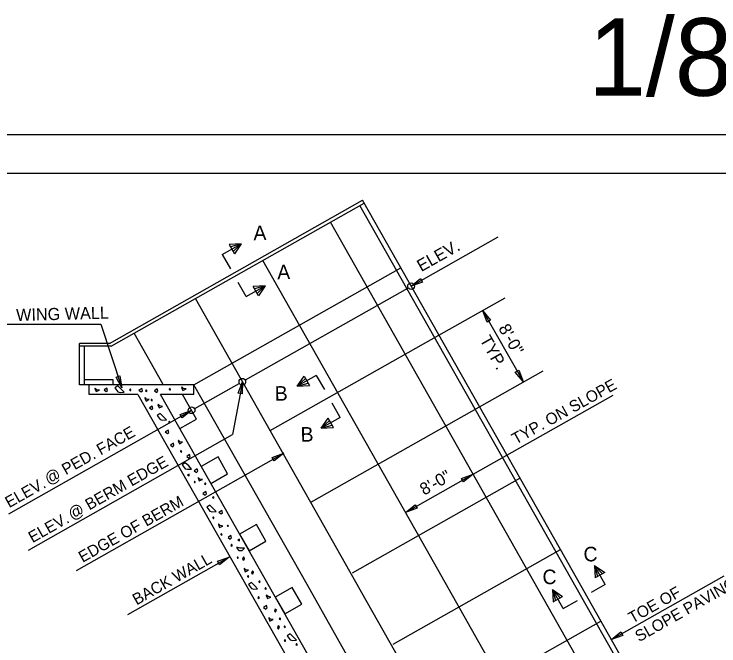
# Model space of a CAD drawing. Extents: x 0 to 272, y 0 to 188.
# Drawn here: x 160.5 to 233.2, y 123.2 to 188.4 of the extents above; entities that cross this region are included whole.
import ezdxf

# ---------------------------------------------------------------- set-up
doc = ezdxf.new("R2010")
doc.units = 0
for name, color, linetype in [('BORDER_ANNO_Cutsheet', 7, 'Continuous'), ('BRDG_ANNO_Anno-Sheet', 7, 'Continuous'), ('BRDG_ANNO_General-Notes', 7, 'Continuous'), ('BRDG_BASE_Hidden-Line', 7, 'Continuous'), ('BRDG_BASE_Obj-Line', 7, 'Continuous'), ('BRDG_BASE_Pattern', 7, 'Continuous')]:
    doc.layers.add(name, color=color, linetype=linetype)

msp = doc.modelspace()

# ---------------------------------------------------------------- linework, layer by layer
at = {"layer": 'BORDER_ANNO_Cutsheet'}
msp.add_lwpolyline([(0, 176), (272, 176), (272, 0), (0, 0)], close=True, dxfattribs=at)
at = {"layer": 'BRDG_ANNO_Anno-Sheet'}
msp.add_lwpolyline([(12, 172), (268, 172), (268, 4), (12, 4)], close=True, dxfattribs=at)
at = {"layer": 'BRDG_ANNO_General-Notes'}
for p, q in [((201.472, 160.347), (210.464, 165.434)), ((182.008, 163.614), (183.967, 164.721)), ((183.967, 164.721), (182.711, 164.657)), ((182.711, 164.657), (182.988, 164.167)), ((183.967, 164.721), (182.849, 164.412)), ((183.967, 164.721), (183.126, 163.923)), ((183.967, 164.721), (183.265, 163.678)), ((182.008, 163.614), (182.839, 162.145)), ((182.988, 164.167), (183.265, 163.678)), ((184.482, 159.277), (183.651, 160.745)), ((201.472, 160.347), (202.458, 161.144)), ((202.663, 160.781), (201.472, 160.347)), ((202.458, 161.144), (202.663, 160.781)), ((184.383, 150.679), (201.141, 160.16)), ((184.482, 159.277), (186.44, 160.385)), ((186.44, 160.385), (185.184, 160.32)), ((185.461, 159.831), (185.184, 160.32)), ((186.44, 160.385), (185.322, 160.075)), ((186.44, 160.385), (185.599, 159.586)), ((186.44, 160.385), (185.738, 159.341)), ((185.738, 159.341), (185.461, 159.831)), ((204.349, 155.289), (211.182, 159.154)), ((208.872, 157.816), (213.011, 150.501)), ((209.306, 156.626), (208.872, 157.816)), ((208.872, 157.816), (209.669, 156.831)), ((159.31, 156.448), (169.479, 156.448)), ((169.479, 156.448), (171.647, 149.848)), ((209.669, 156.831), (209.306, 156.626)), ((208.52, 147.917), (215.09, 151.634)), ((212.214, 151.486), (212.577, 151.691)), ((213.011, 150.501), (212.214, 151.486)), ((212.577, 151.691), (213.011, 150.501)), ((171.059, 150.971), (171.455, 151.101)), ((171.647, 149.848), (171.059, 150.971)), ((171.455, 151.101), (171.647, 149.848)), ((184.075, 150.496), (183.076, 145.034)), ((183.646, 149.304), (184.075, 150.496)), ((184.075, 150.496), (184.055, 149.229)), ((191.698, 151.144), (189.74, 150.036)), ((189.74, 150.036), (190.442, 151.08)), ((189.74, 150.036), (190.581, 150.835)), ((190.442, 151.08), (190.719, 150.59)), ((190.719, 150.59), (190.996, 150.101)), ((191.698, 151.144), (192.529, 149.675)), ((179.17, 147.729), (183.759, 150.326)), ((189.74, 150.036), (190.858, 150.345)), ((189.74, 150.036), (190.996, 150.101)), ((184.055, 149.229), (183.646, 149.304)), ((207.869, 140.944), (222.321, 149.12)), ((194.172, 146.807), (193.341, 148.276)), ((159.984, 136.874), (178.851, 147.549)), ((177.66, 147.114), (178.851, 147.549)), ((178.851, 147.549), (177.865, 146.752)), ((177.865, 146.752), (177.66, 147.114)), ((194.172, 146.807), (192.213, 145.699)), ((192.213, 145.699), (192.915, 146.743)), ((192.213, 145.699), (193.054, 146.498)), ((193.192, 146.253), (192.915, 146.743)), ((193.469, 145.764), (193.192, 146.253)), ((192.213, 145.699), (193.331, 146.008)), ((192.213, 145.699), (193.469, 145.764)), ((162.03, 133.126), (183.076, 145.034)), ((166.973, 131.019), (188.346, 143.111)), ((187.156, 142.677), (188.346, 143.111)), ((187.361, 142.314), (187.156, 142.677)), ((188.346, 143.111), (187.361, 142.314)), ((200.906, 137.005), (207.869, 140.944)), ((206.679, 140.51), (207.869, 140.944)), ((206.884, 140.148), (206.679, 140.51)), ((207.869, 140.944), (206.884, 140.148)), ((200.906, 137.005), (201.892, 137.802)), ((202.097, 137.439), (200.906, 137.005)), ((201.892, 137.802), (202.097, 137.439)), ((172.279, 126.492), (182.719, 132.399)), ((181.529, 131.965), (182.719, 132.399)), ((182.719, 132.399), (181.734, 131.602)), ((181.734, 131.602), (181.529, 131.965)), ((221.498, 129.56), (220.39, 131.519)), ((220.39, 131.519), (220.455, 130.262)), ((220.39, 131.519), (221.434, 130.816)), ((220.39, 131.519), (220.7, 130.401)), ((220.39, 131.519), (221.189, 130.678)), ((221.434, 130.816), (220.944, 130.539)), ((220.944, 130.539), (220.455, 130.262)), ((222.124, 123.881), (233.734, 130.449)), ((221.498, 129.56), (220.03, 128.729)), ((217.161, 127.087), (216.054, 129.046)), ((216.054, 129.046), (217.097, 128.343)), ((216.054, 129.046), (216.118, 127.789)), ((216.054, 129.046), (216.852, 128.205)), ((216.054, 129.046), (216.363, 127.928)), ((216.118, 127.789), (216.607, 128.066)), ((216.607, 128.066), (217.097, 128.343)), ((217.161, 127.087), (218.63, 127.918)), ((222.124, 123.881), (223.11, 124.677)), ((223.315, 124.315), (222.124, 123.881)), ((223.11, 124.677), (223.315, 124.315))]:
    msp.add_line(p, q, dxfattribs=at)
for centre in [(201.468, 160.348), (184.073, 150.497), (178.845, 147.545)]:
    msp.add_circle(centre, 0.343, dxfattribs=at)
at = {"layer": 'BRDG_BASE_Hidden-Line'}
for p, q in [((232.361, 104.751), (196.194, 168.675)), ((167.794, 150.184), (167.794, 154.16)), ((170.754, 150.698), (167.751, 150.698)), ((170.754, 150.198), (170.754, 150.698)), ((190.747, 129.564), (179.081, 150.184)), ((208.113, 98.87), (190.747, 129.564))]:
    msp.add_line(p, q, dxfattribs=at)
at = {"layer": 'BRDG_BASE_Obj-Line'}
for p, q in [((170.375, 154.45), (196.471, 169.214)), ((170.539, 154.16), (196.635, 168.924)), ((216.862, 133.172), (196.471, 169.214)), ((211.299, 134.882), (193.153, 166.955)), ((203.026, 133.258), (186.19, 163.015)), ((179.081, 150.184), (200.41, 162.252)), ((194.706, 131.717), (179.228, 159.076)), ((175.91, 150.223), (172.932, 155.487)), ((186.957, 145.449), (204.349, 155.289)), ((170.375, 154.45), (167.294, 154.45)), ((167.294, 150.184), (167.294, 154.45)), ((170.539, 154.16), (167.294, 154.16)), ((179.081, 150.184), (167.294, 150.184)), ((168.294, 149.184), (168.294, 150.184)), ((179.081, 149.184), (179.081, 150.184)), ((173.296, 149.184), (168.294, 149.184)), ((173.296, 149.182), (201.833, 98.87)), ((179.081, 149.184), (175.637, 149.184)), ((186.426, 130.107), (175.637, 149.177)), ((179.356, 146.642), (177.91, 149.177)), ((191.192, 138.113), (208.52, 147.917)), ((177.631, 145.662), (179.354, 146.645)), ((181.569, 142.728), (179.832, 141.737)), ((182.56, 140.99), (181.569, 142.728)), ((179.832, 141.737), (180.823, 140)), ((179.832, 141.737), (180.823, 140)), ((180.823, 140), (182.56, 140.99)), ((195.435, 130.781), (212.691, 140.544)), ((185.519, 135.77), (183.781, 134.78)), ((186.51, 134.033), (185.519, 135.77)), ((183.781, 134.78), (184.772, 133.042)), ((223.326, 113.625), (211.299, 134.882)), ((184.772, 133.042), (186.51, 134.033)), ((199.612, 123.412), (216.862, 133.172)), ((216.281, 109.83), (203.026, 133.258)), ((232.895, 104.834), (216.862, 133.172)), ((196.852, 127.925), (194.706, 131.717)), ((204.111, 98.849), (186.426, 130.107)), ((189.201, 129.264), (187.463, 128.273)), ((190.192, 127.527), (189.201, 129.264)), ((187.463, 128.273), (188.454, 126.536)), ((212.66, 99.956), (196.839, 127.918)), ((188.454, 126.536), (190.192, 127.527)), ((203.788, 116.043), (221.028, 125.797))]:
    msp.add_line(p, q, dxfattribs=at)
at = {"layer": 'BRDG_BASE_Pattern'}
for points in [[(168.877, 149.779), (169.004, 149.47), (169.333, 149.624), (169.061, 149.672), (168.895, 149.84)], [(169.812, 149.647), (170.04, 149.477), (170.169, 149.598), (170.104, 149.843)], [(170.934, 149.854), (171.241, 149.454), (171.484, 149.387), (171.881, 149.407), (171.589, 149.732), (171.237, 150.066)], [(172.441, 149.627), (172.523, 149.572), (172.577, 149.591), (172.573, 149.61), (172.562, 149.665), (172.532, 149.716), (172.5, 149.715), (172.474, 149.7), (172.466, 149.69), (172.458, 149.664)], [(173.406, 149.612), (173.634, 149.441), (173.763, 149.562), (173.698, 149.807)], [(175.015, 149.554), (175.243, 149.384), (175.372, 149.505), (175.306, 149.749)], [(176.527, 149.698), (176.609, 149.642), (176.662, 149.661), (176.659, 149.68), (176.648, 149.735), (176.618, 149.787), (176.586, 149.785), (176.56, 149.77), (176.552, 149.76), (176.544, 149.734)], [(177.813, 149.906), (177.94, 149.597), (178.269, 149.751), (177.997, 149.798), (177.831, 149.967)], [(174.103, 149.546), (174.186, 149.491), (174.239, 149.509), (174.236, 149.528), (174.225, 149.583), (174.195, 149.635), (174.163, 149.633), (174.137, 149.619), (174.129, 149.608), (174.121, 149.583)], [(174.021, 148.804), (174.148, 148.495), (174.477, 148.649), (174.205, 148.697), (174.039, 148.865)], [(174.659, 148.587), (174.741, 148.531), (174.795, 148.55), (174.791, 148.569), (174.78, 148.624), (174.75, 148.676), (174.718, 148.674), (174.692, 148.659), (174.684, 148.649), (174.676, 148.623)], [(174.498, 147.788), (174.726, 147.618), (174.855, 147.739), (174.789, 147.983)], [(175.37, 148.108), (175.497, 147.799), (175.826, 147.953), (175.553, 148.001), (175.388, 148.169)], [(175.295, 146.999), (175.603, 146.599), (175.846, 146.532), (176.243, 146.552), (175.95, 146.877), (175.599, 147.211)], [(176.478, 146.296), (176.56, 146.24), (176.614, 146.259), (176.61, 146.278), (176.599, 146.333), (176.57, 146.385), (176.537, 146.383), (176.511, 146.368), (176.503, 146.358), (176.495, 146.332)], [(176.127, 145.314), (176.355, 145.144), (176.485, 145.265), (176.419, 145.509)], [(176.669, 143.956), (176.897, 143.786), (177.026, 143.907), (176.961, 144.151)], [(177.46, 144.403), (177.587, 144.094), (177.916, 144.248), (177.643, 144.295), (177.478, 144.464)], [(177.688, 143.286), (177.771, 143.23), (177.824, 143.249), (177.82, 143.268), (177.809, 143.323), (177.78, 143.375), (177.747, 143.373), (177.721, 143.358), (177.713, 143.348), (177.705, 143.322)], [(178.344, 142.781), (178.572, 142.611), (178.701, 142.732), (178.636, 142.977)], [(177.886, 141.922), (178.193, 141.521), (178.436, 141.454), (178.833, 141.475), (178.541, 141.8), (178.189, 142.134)], [(179.117, 141.3), (179.345, 141.13), (179.474, 141.251), (179.409, 141.496)], [(178.416, 140.874), (178.585, 140.792), (178.593, 140.947)], [(179.507, 140.562), (179.634, 140.253), (179.963, 140.407), (179.691, 140.455), (179.525, 140.623)], [(179.095, 140.159), (179.138, 140.09), (179.193, 140.101), (179.219, 140.14), (179.213, 140.168), (179.181, 140.19), (179.16, 140.195), (179.132, 140.19)], [(180.172, 139.946), (180.255, 139.89), (180.308, 139.909), (180.304, 139.928), (180.293, 139.983), (180.264, 140.035), (180.232, 140.033), (180.206, 140.018), (180.198, 140.008), (180.19, 139.982)], [(180.016, 138.971), (180.244, 138.801), (180.373, 138.922), (180.307, 139.167)], [(180.959, 138.556), (181.127, 138.474), (181.136, 138.629)], [(180.417, 137.544), (180.725, 137.143), (180.968, 137.076), (181.365, 137.097), (181.072, 137.422), (180.721, 137.756)], [(181.663, 137.028), (181.891, 136.857), (182.02, 136.978), (181.954, 137.223)], [(181.015, 136.433), (181.097, 136.378), (181.151, 136.397), (181.147, 136.415), (181.136, 136.471), (181.107, 136.522), (181.074, 136.52), (181.048, 136.506), (181.04, 136.496), (181.032, 136.47)], [(181.607, 135.757), (181.734, 135.448), (182.063, 135.602), (181.791, 135.65), (181.625, 135.818)], [(182.511, 135.644), (182.553, 135.575), (182.609, 135.586), (182.634, 135.625), (182.629, 135.653), (182.596, 135.675), (182.576, 135.68), (182.547, 135.675)], [(181.85, 134.723), (181.932, 134.668), (181.985, 134.686), (181.982, 134.705), (181.971, 134.76), (181.941, 134.812), (181.909, 134.81), (181.883, 134.796), (181.875, 134.785), (181.867, 134.76)], [(182.6, 134.433), (182.828, 134.263), (182.957, 134.384), (182.892, 134.629)], [(183.596, 134.164), (183.765, 134.082), (183.773, 134.237)], [(182.894, 133.596), (182.977, 133.54), (183.03, 133.559), (183.026, 133.578), (183.015, 133.633), (182.986, 133.685), (182.953, 133.683), (182.928, 133.669), (182.92, 133.658), (182.912, 133.632)], [(183.49, 133.306), (183.705, 133.09), (184.058, 133.092), (184.298, 133.329), (183.858, 133.307), (183.493, 133.416)], [(183.53, 132.344), (183.572, 132.275), (183.627, 132.286), (183.653, 132.325), (183.648, 132.353), (183.615, 132.375), (183.595, 132.38), (183.566, 132.375)], [(184.1, 132.187), (184.217, 132.076), (184.299, 132.245), (184.307, 132.304), (184.19, 132.415)], [(184.247, 131.191), (184.374, 130.883), (184.703, 131.037), (184.431, 131.084), (184.265, 131.252)], [(185.017, 130.751), (185.133, 130.64), (185.215, 130.809), (185.223, 130.868), (185.106, 130.979)], [(184.6, 130.383), (184.683, 130.327), (184.736, 130.346), (184.732, 130.365), (184.721, 130.42), (184.692, 130.472), (184.659, 130.47), (184.633, 130.455), (184.626, 130.445), (184.618, 130.419)], [(184.702, 129.562), (185.009, 129.161), (185.252, 129.094), (185.649, 129.115), (185.357, 129.44), (185.005, 129.774)], [(185.766, 129.844), (185.849, 129.789), (185.902, 129.808), (185.898, 129.827), (185.888, 129.882), (185.858, 129.933), (185.826, 129.932), (185.8, 129.917), (185.792, 129.907), (185.784, 129.881)], [(186.402, 129.134), (186.485, 129.078), (186.538, 129.097), (186.535, 129.116), (186.524, 129.171), (186.494, 129.223), (186.462, 129.221), (186.436, 129.206), (186.428, 129.196), (186.42, 129.17)], [(185.684, 128.196), (185.766, 128.14), (185.82, 128.159), (185.816, 128.178), (185.805, 128.233), (185.775, 128.285), (185.743, 128.283), (185.717, 128.268), (185.709, 128.258), (185.701, 128.232)], [(186.543, 128.426), (186.67, 128.117), (186.999, 128.271), (186.726, 128.318), (186.561, 128.487)], [(186.26, 127.203), (186.488, 127.033), (186.618, 127.154), (186.552, 127.399)], [(187.38, 126.815), (187.497, 126.704), (187.578, 126.873), (187.586, 126.932), (187.47, 127.042)], [(186.79, 126.099), (186.917, 125.79), (187.246, 125.944), (186.973, 125.992), (186.807, 126.16)], [(187.882, 126.008), (187.965, 125.953), (188.018, 125.972), (188.014, 125.991), (188.003, 126.046), (187.974, 126.097), (187.941, 126.096), (187.916, 126.081), (187.908, 126.071), (187.9, 126.045)], [(187.685, 125.07), (187.802, 124.959), (187.883, 125.128), (187.891, 125.187), (187.775, 125.298)], [(188.372, 125.19), (188.455, 125.135), (188.508, 125.154), (188.504, 125.172), (188.494, 125.228), (188.464, 125.279), (188.431, 125.277), (188.406, 125.263), (188.398, 125.253), (188.39, 125.227)], [(188.7, 124.265), (189.008, 123.864), (189.25, 123.797), (189.647, 123.818), (189.355, 124.143), (189.003, 124.477)], [(188.386, 123.766), (188.469, 123.71), (188.522, 123.729), (188.519, 123.748), (188.508, 123.803), (188.478, 123.855), (188.446, 123.853), (188.42, 123.838), (188.412, 123.828), (188.404, 123.802)], [(189.597, 123.351), (189.68, 123.295), (189.733, 123.314), (189.73, 123.333), (189.719, 123.388), (189.689, 123.439), (189.657, 123.438), (189.631, 123.423), (189.623, 123.413), (189.615, 123.387)]]:
    msp.add_lwpolyline(points, close=True, dxfattribs=at)

# ---------------------------------------------------------------- texts
at = {"layer": 'BRDG_ANNO_Anno-Sheet'}
msp.add_text('1/8"=1\'-0"', height=8, dxfattribs=at).set_placement((219.734, 180))
at = {"layer": 'BRDG_ANNO_General-Notes'}
for s, height, rotation, p in [('A', 1.5, 1.1, (185.228, 165.088)), ('ELEV.', 1.25, 29.49987, (202.522, 161.797)), ('A', 1.5, 1.1, (187.681, 161.053)), ('WING WALL', 1.2499, 1.46647, (160.768, 156.756)), ('8\'-0"', 1.25, 299.50061, (210.434, 156.017)), ('TYP.', 1.25, 299.50061, (208.513, 154.834)), ('TYP. ON SLOPE', 1.18183, 29.02896, (212.265, 143.983)), ('B', 1.5, 1.1, (187.424, 148.527)), ('@ PED. FACE', 1.18183, 29.51807, (164.097, 139.832)), ('B', 1.5, 1.1, (190.088, 144.301)), ('@ BERM EDGE', 1.18185, 29.51762, (166.516, 136.197)), ('8\'-0"', 1.25, 29.49946, (202.818, 138.729)), ('ELEV.', 1.1818, 29.51768, (160.031, 137.441)), ('EDGE OF BERM', 1.18183, 29.51749, (167.604, 131.798)), ('ELEV.', 1.1819, 29.51768, (162.435, 133.829)), ('C', 1.5, 1.1, (219.259, 131.944)), ('BACK WALL', 1.1818, 29.51764, (173.17, 127.406)), ('C', 1.5, 1.1, (215.033, 129.594)), ('SLOPE PAVING', 1.18183, 29.5288, (224.98, 123.608)), ('TOE OF', 1.1819, 29.52898, (224.292, 125.517))]:
    msp.add_text(s, height=height, rotation=rotation, dxfattribs=at).set_placement(p)

doc.saveas('drawing.dxf')
